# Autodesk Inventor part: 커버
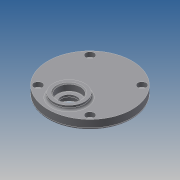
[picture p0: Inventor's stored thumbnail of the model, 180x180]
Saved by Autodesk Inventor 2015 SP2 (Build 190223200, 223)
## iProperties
Created: 2015-06
Part Number: 커버
Material: 일반
Document SubType Name: Modeling
Designer: AMC
Density: 1 g/cm^3
Appearance: 기본값
Author: AMC
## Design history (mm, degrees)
sketch "스케치1"
  geometry: C1 r 40 at (0, 0); 1 further point
  constraints: 1 centre point, 1 coincident
  dimensions: "d0" = 80 diameter of C1
extrude "돌출1" new body sketch "스케치1" distance "d1" = 9; taper "d2" = 0 deg
sketch "스케치2"
  geometry: C1 r 40 at (0, 0) reference; C2 r 15 at (0, -20); 1 further point
  constraints: 1 centre point, 1 vertical alignment
  dimensions: "d3" = 30 diameter of C2; "d4" = 20 distance of point (0, 0) C2.centre
extrude "돌출2" join sketch "스케치2" distance "d5" = 4; taper "d6" = 0 deg
sketch "스케치3"
  geometry: C1 r 14 at (0, -20); C2 r 14 at (0, 11); 1 further point
  constraints: 2 centre point, 2 vertical alignment
  dimensions: "d7" = 28 diameter of C1; "d8" = 20 distance of point (0, 0) C1.centre; "d9" = 11 distance of point (0, 0) C2.centre; "d10" = 28 diameter of C2
extrude "돌출3" join sketch "스케치3" distance "d11" = 3; taper "d12" = 0 deg
hole "구멍1" diameter "d15" = 15; stored, may be unused: countersink angle "d19" = 90 deg, drill point angle "d21" = 118 deg; dims "d13" = 10, "d14" = 10, "d16" = 6, "d17" = 22, "d18" = 7, "d20" = 8
node "작업 평면1"
sketch "스케치4"
  geometry: C1 r 14 at (0, 0) reference; C2 r 11 at (0, 0); 1 further point
  constraints: 1 centre point, 1 coincident
  dimensions: "d22" = 22 diameter of C2
extrude "돌출4" cut sketch "스케치4" distance "d23" = 7; taper "d24" = 0 deg
sketch "스케치5"
  geometry: C1 r 11 at (0, 0) reference; C2 r 9 at (0, 0); 1 further point
  constraints: 1 centre point, 1 coincident
  dimensions: "d25" = 18 diameter of C2
extrude "돌출5" cut sketch "스케치5" distance "d26" = 1; taper "d27" = 0 deg
fillet "모깎기1" dims "d28" = 1, "d29" = 0.3
chamfer "모따기1" distance "d30" = 1; stored, may be unused: second distance "d31" = 2, angle "d32" = 45 deg
sketch "스케치7"
  geometry: L1 (0, 0)-(-21.753, 0); 2 further points
  constraints: 2 end point, 1 coincident, 1 horizontal
  dimensions: "d35" = 45 deg dimension on L1.start L1.end point (-24.749, 24.749); "d36" = 35 distance of L1.start point (-24.749, 24.749)
hole "구멍2" sketch "스케치7" at (-24.749, 24.749) diameter "d37" = 4.5; stored, may be unused: countersink angle "d41" = 90 deg, drill point angle "d43" = 0 deg; dims "d38" = 6, "d39" = 8, "d40" = 4.4, "d42" = 8
fillet "모깎기2" dims "d47" = 2
node "솔리드1"
mirror "대칭1"
pattern_circular "원형 패턴1" dims angle "d45" = 360 deg
node "투영된 루프1"
node "투영된 루프2"
node "투영된 루프3"
